Omron Sysmac Studio project ModbusTCP通讯 (Sysmac Studio 1.25.1.0, StandardProject)

# Controller new_Controller_0: NX1P2-9024DT version 1.16
Task PrimaryTask (priority 4, period or condition 2000): Program0

TYPE TYPE_BD4543 : STRUCT
    PV : ARRAY[0..15] OF INT;  (* 实际温度、报警状态、故障状态（只读） *)
    RUNF : INT;  (* 通道故障（只读） *)
    ALF1 : INT;  (* 报警1状态（只读） *)
    ALF2 : INT;  (* 报警2状态（只读） *)
    ONB : INT;  (* 启动温控（可读可写，有变化自动写入模块） *)
    ATUB : INT;  (* 自整定（可读可写，有变化自动写入模块） *)
    SV : ARRAY[0..15] OF INT;  (* 设定温度（可读可写，有变化自动写入模块） *)
    Pb : ARRAY[0..15] OF INT;  (* 温度偏置（可读可写，有变化自动写入模块） *)
    running : INT;  (* 通信计数 *)
    error : INT;  (* 通信故障计数 *)
    tmp : ARRAY[0..34] OF INT;  (* 中间数据（不要修改这些数据） *)
END_STRUCT END_TYPE
TYPE BD4241 : STRUCT
    PV : ARRAY[0..15] OF INT;  (* 实际温度（只读） *)
    running : INT;
    error : INT;
END_STRUCT END_TYPE

VAR_GLOBAL
    P1 : _sDEVICE_PORT;
    P0 : _sDEVICE_PORT;
END_VAR
VAR_GLOBAL CONSTANT
    Port1 : _sNXUNIT_ID := (NodeAdr := 65535, IPAdr := [5(16#FF)], UnitNo := 1, Path := [16#1, 16#0, 16#2, 16#0, 16#1, 59(16#0)], PathLength := 6);
END_VAR
VAR_GLOBAL
    BD4543 : ARRAY[0..9] OF TYPE_BD4543;  (* 数组与模块个数一致！！！; published *)
END_VAR
VAR_GLOBAL CONSTANT
    Port0 : _sOPTBOARD_ID := (SlotNo := 1, IPAdr := [5(16#0)]);
END_VAR

PROGRAM Program0
VAR
    abc : BOOL;
    HL : ModbusTCP;
END_VAR

(* Section Section0: ladder, written here as Structured Text *)

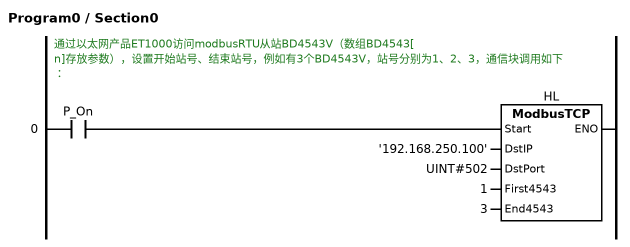
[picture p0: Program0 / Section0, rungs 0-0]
(* Rung 0: 通过以太网产品ET1000访问modbusRTU从站BD4543V（数组BD4543[n]存放参数），设置开始站号、结束站号，例如有3个BD4543V，站号分别为1、2、3，通信块调用如下： *)
HL(Start := P_On, DstIP := '192.168.250.100', DstPort := UINT#502, First4543 := 1, End4543 := 3);
END_PROGRAM

FUNCTION_BLOCK ModbusTCP
VAR
    Trigger : BOOL := False;
    DoTCP : BOOL := False;
    Stage : INT := 0;
    SktTCPConnect_instance : SktTCPConnect;
    SktClearBuf_instance : SktClearBuf;
    SktGetTCPStatus_instance : SktGetTCPStatus;
    SktTCPSend_instance : SktTCPSend;
    SktTCPRcv_instance : SktTCPRcv;
    SktClose_instance : SktClose;
    WkSocket : _sSOCKET := (Handle := 0, SrcAdr := (PortNo := 0, IpAdr := ''), DstAdr := (PortNo := 0, IpAdr := ''));
    Working : BOOL := False;
    TON_instance : TON;
    Delay : TIME := T#100MS;
    Stage1 : INT := 0;  (* 通信状态 *)
    TypeNum : INT := 0;  (* 从站类型代号 *)
    Index : INT;  (* 索引 *)
    CurrentSlave : USINT;  (* 当前通信的从站ID *)
    TransID : UINT := 0;  (* 事务标识 *)
    SendSize : UINT;
    RcvSize : UINT;
    i : INT;
    j : INT;
    k : INT;
    temp : INT;
    ABC : SINT;
    Connect : BOOL;
    ClearBuf : BOOL;
    GetStatus : BOOL;
    Send_On : BOOL;
    Recive_On : BOOL;
    Close : BOOL;
    SendSocketDat : ARRAY[0..299] OF BYTE := [300(16#0)];
    RcvSocketDat : ARRAY[0..299] OF BYTE := [300(16#0)];
END_VAR
VAR_INPUT
    Start : BOOL;
    DstIP : STRING[50];
    DstPort : UINT;
    First4543 : USINT;  (* 首个4543站号 *)
    End4543 : USINT;  (* 末个4543站号 *)
END_VAR
VAR_EXTERNAL CONSTANT
    _EIP_EtnOnlineSta : BOOL;
END_VAR
VAR_EXTERNAL
    BD4543 : ARRAY[0..9] OF TYPE_BD4543;
END_VAR
//--------------------------------------------------------ModbusTCP数据包处理-------------------------------------------------//

// ET1000是以太网转RS485产品，通过ModbusTCP协议访问RS485总线上的modbus-RTU从站。
IF Start =FALSE THEN
	Stage1:=0;
END_IF;

CASE Stage1 OF
	0 :		// 初始状态
		IF Start =TRUE THEN 
			TypeNum := 0;  //0:4543  1:4340 
			Stage1 := INT#1;
		END_IF;
	
	1 :		// 从站类型切换
		IF (TypeNum = 0) AND (First4543>0) AND (End4543>=First4543) AND (End4543<255) THEN	//BD4543通信开始
			CurrentSlave:=First4543;
			Index:=0;
			Stage1:=INT#2;	
		//ELSIF (TypeNum=1) AND First4340>0 AND End4340>=First4340 AND End4340<255 THEN 
		//	CurrentSlave:=First4340;
		//	Index:=0;
		//	Stage1:=10;	
		END_IF;
		
	2 :		// BD4543通信处理开始，读通信modbus寄存器3000~3052
		temp:=TransID/256;
		SendSocketDat[0]:=UINT_TO_BYTE(temp);//事务标识 ，高字节
		SendSocketDat[1]:=UINT_TO_BYTE(TransID);//低字节
		SendSocketDat[2]:=16#0;//ModbusTCP协议标识（固定为0），高字节
		SendSocketDat[3]:=16#0;//低字节
		SendSocketDat[4]:=16#0;//PDU字节数，高字节
		SendSocketDat[5]:=16#6;//低字节
		SendSocketDat[6]:=USINT_TO_BYTE(CurrentSlave);//站号
		SendSocketDat[7]:=16#03;//功能码，03
		SendSocketDat[8]:=16#0B;//读寄存器开始地址（3000），高字节，
		SendSocketDat[9]:=16#B8;//低字节
		SendSocketDat[10]:=16#0;//读寄存器个数（53个），高字节，
		SendSocketDat[11]:=16#35;//低字节
		SendSize:=12;	//发送12个字节请求
		RcvSize:=115;	//将收到115个字节的回复*********************
		IF Stage=5 THEN 
			Working :=TRUE;//启动TCP发送
			Stage1:=INT#3;
		END_IF;
		
	3 :		// TCP收发完成，提取数据
		IF (Working=FALSE) THEN
			Stage1 := 4;
			IF SendSocketDat[0]=RcvSocketDat[0] AND SendSocketDat[1]=RcvSocketDat[1] AND RcvSocketDat[5]=109 THEN	//事务号一致、PDU字节数53*2+3=109
				
				// 取BD4543V的16路PV  (只读)
				FOR i:=0 TO 15 DO 
					j:=i*2+9;	//数据高字节、低字节：RcvSocketDat[9]、RcvSocketDat[10]、、、、
					BD4543[Index].PV[i] :=  BYTE_TO_UINT(RcvSocketDat[j]) *256 + BYTE_TO_UINT(RcvSocketDat[j+1]) ;
				END_FOR;
				
				// RUNF、ALF1、ALF2  (只读)
				BD4543[Index].RUNF := (BYTE_TO_UINT(RcvSocketDat[41]) *256 + BYTE_TO_UINT(RcvSocketDat[42]));
				BD4543[Index].ALF1 := BYTE_TO_UINT(RcvSocketDat[43]) *256 + BYTE_TO_UINT(RcvSocketDat[44]);
				BD4543[Index].ALF2 := BYTE_TO_UINT(RcvSocketDat[45]) *256 + BYTE_TO_UINT(RcvSocketDat[46]);
				
				// ONB ATUB SV PB  (可读可写，有变化更新)
				temp := BYTE_TO_UINT(RcvSocketDat[47])*256  + BYTE_TO_UINT(RcvSocketDat[48]);	//ONB
				IF BD4543[Index].tmp[0] <> temp THEN
					BD4543[Index].tmp[0] := temp;
					BD4543[Index].ONB := temp;
				END_IF;
				temp := BYTE_TO_UINT(RcvSocketDat[49])*256  + BYTE_TO_UINT(RcvSocketDat[50]);	//ATUB
				IF BD4543[Index].tmp[1] <> temp THEN
					BD4543[Index].tmp[1] := temp;
					BD4543[Index].ATUB := temp;
				END_IF;

				FOR i:=0 TO 15 DO 
					j:=i*2+51;	//数据高字节、低字节：RcvSocketDat[51]、RcvSocketDat[52]、、、、
					temp := BYTE_TO_UINT(RcvSocketDat[j])*256  + BYTE_TO_UINT(RcvSocketDat[j+1]);	//SV
					IF BD4543[Index].tmp[i+2] <> temp THEN
						BD4543[Index].tmp[i+2] := temp;
						BD4543[Index].SV[i] := temp;
					END_IF;
					j:=i*2+83;	//数据高字节、低字节：RcvSocketDat[83]、RcvSocketDat[84]、、、、
					temp := BYTE_TO_UINT(RcvSocketDat[j])*256  + BYTE_TO_UINT(RcvSocketDat[j+1]);	//Pb
					IF BD4543[Index].tmp[i+18] <> temp THEN
						BD4543[Index].tmp[i+18] := temp;
						BD4543[Index].Pb[i] := temp;
					END_IF;
				END_FOR;
			ELSE
				Stage1:=7;	//读通信故障
			END_IF;
		END_IF;
	
	4 :		// 写通信准备
		// 检查数据是否有变化
		k :=0;
		IF (BD4543[Index].ONB<>BD4543[Index].tmp[0]) OR  (BD4543[Index].ATUB<>BD4543[Index].tmp[1]) THEN
			k := k+1;
		END_IF;
		FOR i:=0 TO 15 DO
			IF (BD4543[Index].SV[i]<>BD4543[Index].tmp[i+2]) OR (BD4543[Index].Pb[i]<>BD4543[Index].tmp[i+18])  THEN
				k:=k+1;
			END_IF;
		END_FOR;
		IF k = 0 THEN //无变化，跳过写
			Stage1 := 6;

		ELSE	// 有变化，准备数据，写modbus寄存器3019~3052
			SendSocketDat[0]:=UINT_TO_BYTE(TransID/256);//事务标识 ，高字节
			SendSocketDat[1]:=UINT_TO_BYTE(TransID);//低字节
			SendSocketDat[2]:=16#0;//ModbusTCP协议标识（固定为0），高字节
			SendSocketDat[3]:=16#0;//低字节
			SendSocketDat[4]:=16#0;//PDU字节数，高字节		//总字节数=7+chs*2 = 75
			SendSocketDat[5]:=16#4B;//低字节
			SendSocketDat[6]:=USINT_TO_BYTE(CurrentSlave);//站号
			SendSocketDat[7]:=16#10;//功能码，03
			SendSocketDat[8]:=16#0B;//读寄存器开始地址（3019），高字节，
			SendSocketDat[9]:=16#CB;//低字节
			SendSocketDat[10]:=16#0;//读寄存器个数（34个），高字节，
			SendSocketDat[11]:=16#22;//低字节
			SendSocketDat[12]:=16#44;
			SendSocketDat[13]:=UINT_TO_BYTE(INT_TO_UINT(BD4543[Index].ONB)/256);
			SendSocketDat[14]:=UINT_TO_BYTE(BD4543[Index].ONB);
			SendSocketDat[15]:=UINT_TO_BYTE(INT_TO_UINT(BD4543[Index].ATUB)/256);
			SendSocketDat[16]:=UINT_TO_BYTE(BD4543[Index].ATUB);
			FOR i:=0 TO 15 DO
				j:=i*2+17;
				SendSocketDat[j]:=UINT_TO_BYTE(INT_TO_UINT(BD4543[Index].SV[i])/256);
				SendSocketDat[j+1]:=UINT_TO_BYTE(BD4543[Index].SV[i]);
				j:=i*2+49;
				SendSocketDat[j]:=UINT_TO_BYTE(INT_TO_UINT(BD4543[Index].Pb[i])/256);
				SendSocketDat[j+1]:=UINT_TO_BYTE(BD4543[Index].Pb[i]);				
			END_FOR;			
			SendSize:=81;	//发送81个字节请求
			RcvSize:=12;	//将收到12个字节的回复
			
			Working:=TRUE; // TCP通信开始
			Stage1:=INT#5;
		END_IF;
		
	5 :		// TCP收发完成，写完成处理
		IF Working=FALSE THEN
			Stage1 := 6;
			IF SendSocketDat[0]=RcvSocketDat[0] AND SendSocketDat[1]=RcvSocketDat[1] AND RcvSocketDat[5]=6 THEN	//事务号一致，PDU字节数=6
				FOR i:=0 TO 33 DO
					j:=i*2+13;
					BD4543[Index].tmp[i]:=BYTE_TO_UINT(SendSocketDat[j])*256+BYTE_TO_UINT(SendSocketDat[j+1]);
				END_FOR;
			ELSE
				Stage1:=7;//写通信故障
			END_IF;
		END_IF;
		
	6 :		// 正常完成
		BD4543[Index].running:=BD4543[Index].running+1;
		BD4543[Index].error:=0;
		Stage1:=8;
		
	7 : 	//	故障状态
		BD4543[Index].running:=BD4543[Index].running+1;
		BD4543[Index].error:=BD4543[Index].error+1;
		Stage1:=8;
	
	8 :		//切换下个站
		CurrentSlave:=CurrentSlave+1;
		Index:=Index+1;
		IF CurrentSlave<=End4543 THEN
			Stage1:=2;
		ELSE
			Stage1:=1;
			TypeNum:=0;
		END_IF;
		
ELSE
	Stage1:=0;;

END_CASE ;
	

//--------------------------------------------------------TCP连接及收发控制-------------------------------------------------//
IF (Start=TRUE) AND (_Eip_EtnOnlineSta=TRUE) AND (DoTCP=FALSE) THEN 
	TON_instance(In:=TRUE, PT:=Delay, Q=>Trigger);	// 延时
ELSE
	TON_instance(In:=FALSE, Q=>Trigger);
END_IF;
IF Trigger=TRUE THEN
	DoTCP:=TRUE;
END_IF;
IF DoTCP=FALSE THEN
		Connect:=FALSE;
		ClearBuf:=FALSE;
		GetStatus:=FALSE;
		Send_On:=FALSE;
		Recive_On:=FALSE;
		Close:=FALSE;
		Stage:=0;
ELSE
    CASE Stage OF 
   	0 :    // 建立连接
       	Connect:=TRUE;
		Stage:=1;
	1 :		// 连接成功，清除接收区
		IF (SktTCPConnect_instance.Done=TRUE) THEN 
              Stage:=INT#2;     // Normal end 
			  Connect:=FALSE;
		END_IF;
        IF (SktTCPConnect_instance.Error=TRUE) THEN 
              Stage:=INT#10;    // Error end 
			  Connect:=FALSE;
        END_IF; 
	2 :		// 清除接收区
		ClearBuf:=TRUE;	
		Stage:=INT#3;
   	3 :   // 成功，读TCP状态
       IF (SktClearBuf_instance.Done=TRUE) THEN // Normal end 
           	Stage:=INT#4;         
		  	ClearBuf:=FALSE;
			GetStatus:=TRUE;
       ELSIF (SktClearBuf_instance.Error=TRUE) THEN // Error end 
           	Stage:=INT#8;        
       END_IF; 
   	4 :    // 读取TCP状态值
       IF (SktGetTCPStatus_instance.Done=TRUE) THEN // Normal end 
           Stage:=INT#5;         
		   GetStatus:=FALSE;
		   Send_On:=FALSE;
		   Recive_On:=FALSE;
       ELSIF (SktGetTCPStatus_instance.Error=TRUE) THEN // Error end
           Stage:=INT#8;         
       END_IF; 
  	5 :		// -----------------------TCP发送数据
		IF (Working=TRUE) THEN
			TransID:=TransID+1;
			Send_On:=TRUE;
			Stage:=INT#6; 
		END_IF;
	6 :    // 发送完成
       IF (SktTCPSend_instance.Done=TRUE) THEN  // Normal end 
		   Send_On:=FALSE;
		   Recive_On:=TRUE;
           Stage:=INT#7;             
       ELSIF (SktTCPSend_instance.Error=TRUE) THEN   // Error end 
           Stage:=INT#8;           
       END_IF; 
  	7 : 	//TCP接收数据
       IF (SktTCPRcv_instance.Done=TRUE) THEN    // Normal end 
		   	Recive_On:=FALSE;
		 	Working:=FALSE;	   
           	Stage:=INT#5;           
       ELSIF (SktTCPRcv_instance.Error=TRUE) THEN   // Error end 
           Stage:=INT#8;           
       END_IF; 
	 
   	8 :    // 关闭连接
       	Close:=TRUE;
  		Stage:=INT#9; 
	9 :  	// 
       IF (SktClose_instance.Done=TRUE) THEN    // Normal end 
		   Close:=FALSE;
           Stage:=INT#0;       
       ELSIF (SktClose_instance.Error=TRUE) THEN   // Error end 
           Stage:=INT#40;           
       END_IF; 
  
   ELSE   // 故障状态
       DoTCP   :=FALSE; 
   END_CASE; 
END_IF; 

//-------------------------------使用的TCP通信相关实例--------------------------
	SktTCPConnect_instance( 
           	Execute   :=Connect, 
			SrcTcpPort:=UINT#0,          // 本地端口号自动分配. 
			DstAdr    :=DstIP, // 远端IP ---------------------根据实际设置
			DstTcpPort:=DstPort,       // 远端 TCP 端口号 
			Socket     =>WkSocket); // Socket 
	SktClearBuf_instance( 
           Execute:=ClearBuf, 
           Socket :=WkSocket);   // Socket 
	SktGetTCPStatus_instance( 
           Execute:=GetStatus, 
           Socket :=WkSocket);   // Socket 
	SktTCPSend_instance( 
           Execute:=Send_On, 
           Socket :=WkSocket,         // Socket 
           SendDat:=SendSocketDat[0], // Send data 
           Size   :=SendSize);       // Send data size 
	SktTCPRcv_instance( 
           Execute:=Recive_On, 
           Socket :=WkSocket,         // Socket 
           TimeOut:=UINT#0,           // Timeout time 
           Size   :=RcvSize,        // Receive data size 
           RcvDat :=RcvSocketDat[0]); // Receive data 
	SktClose_instance( 
           Execute:=Close, 
           Socket :=WkSocket);        // Socket 
		   

//-------------------------------------------------------------------------------------------------------------------------//
END_FUNCTION_BLOCK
